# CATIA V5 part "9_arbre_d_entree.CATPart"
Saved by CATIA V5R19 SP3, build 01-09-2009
Part number: 9_arbre_d_entree
Bounding box of the stored display mesh (mm): x -24.865 to 24.865, y 0 to 113, z -24.997 to 24.997
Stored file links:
  C:\Users\Frédéric\Documents\WF\STSCPI 09-11\Projets\Projet multiplicateur eolienne\Maquette eolienne\9_arbre_d_entree.CATPart
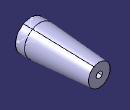
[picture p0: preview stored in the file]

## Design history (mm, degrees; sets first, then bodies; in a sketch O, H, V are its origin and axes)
AxisSystem1: origin (0, 0, 0), X (1, 0, 0), Y (0, 1, 0), Z (0, 0, 1)
Body1 (main body)
  Sketch1 on YZ plane of AxisSystem1, origin (0, 0, 0), H (0, 1, 0), V (0, 0, 1)
    line L1 (0, 0) -> (0, 25)
    line L2 (0, 25) -> (15, 25)
    point P2 (15, 25)
    line L3 (15, 25) -> (113, 18)
    line L4 (113, 18) -> (113, 0)
    line L5 (113, 0) -> (0, 0)
    length L4 = 18
    length L1 = 25
    distance L4 P2 = 98
    length L2 = 15
    vertical: L1 V, L4 V
    horizontal: L2 H, L5 H
  Shaft1 "Bout conique de l'arbre": profile Sketch1, axis Sketch1.L5, angle 360
  Sketch2 on face of Shaft1 from Sketch1.L4, origin (0, 113, 0), H (1, 0, 0), V (0, 0, -1)
    point P1 (0, 0)
  Hole1: placed by Sketch2, at (0, 113, 0) direction (0, -1, 0), diameter 10.106, depth 52, V-bottom angle 120, threaded "M12", thread diameter 12, thread depth 44, pitch 1.75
